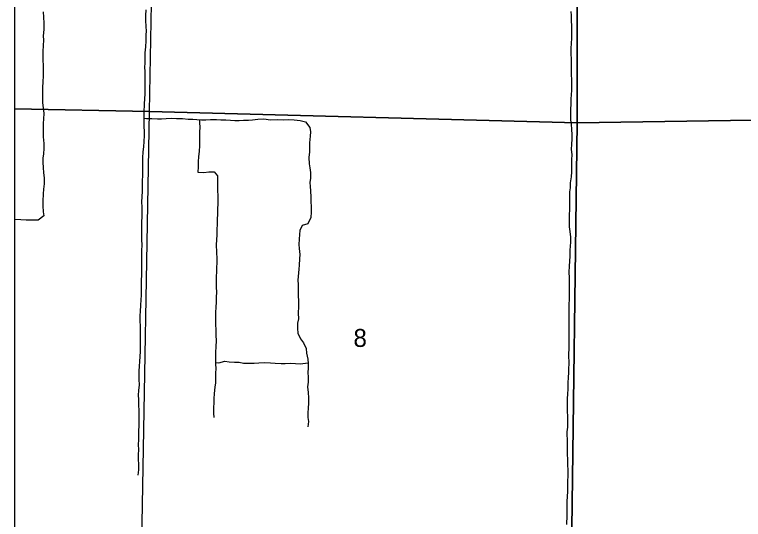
# Model space of a CAD drawing. Extents: x 1772825 to 1773716, y 1138558 to 1139032.
# Drawn here: x 1772825.358 to 1772826.207, y 1138563.179 to 1138563.767 of the extents above; entities that cross this region are included whole.
import ezdxf

# ---------------------------------------------------------------- set-up
doc = ezdxf.new("R2010")
doc.units = 0
for name, color, linetype in [('GM_X_Minor_River', 7, 'Continuous'), ('GM_X_Section', 7, 'Continuous'), ('GM_X_Section_Text', 7, 'Continuous'), ('GM_X_Township', 7, 'Continuous')]:
    doc.layers.add(name, color=color, linetype=linetype)

msp = doc.modelspace()

# ---------------------------------------------------------------- linework, layer by layer
at = {"layer": 'GM_X_Minor_River'}
for points in [[(1772825.51054, 1138563.77204), (1772825.51032, 1138563.76559), (1772825.51029, 1138563.76009), (1772825.51083, 1138563.75231), (1772825.511, 1138563.74757), (1772825.51079, 1138563.74282), (1772825.51057, 1138563.73599), (1772825.51016, 1138563.72917), (1772825.50975, 1138563.72215), (1772825.50953, 1138563.71494), (1772825.50951, 1138563.71001), (1772825.5093, 1138563.70527), (1772825.50947, 1138563.70034), (1772825.50938, 1138563.68004), (1772825.50955, 1138563.67397), (1772825.50934, 1138563.66904), (1772825.50893, 1138563.6624), (1772825.50851, 1138563.65292), (1772825.5083, 1138563.6478), (1772825.50827, 1138563.64097), (1772825.50844, 1138563.63604), (1772825.50861, 1138563.63091), (1772825.50877, 1138563.62598), (1772825.50836, 1138563.61877), (1772825.50796, 1138563.6127), (1772825.50737, 1138563.60664), (1772825.50696, 1138563.59981), (1772825.50675, 1138563.59488), (1772825.50672, 1138563.58957), (1772825.50689, 1138563.58426), (1772825.50687, 1138563.57932), (1772825.50665, 1138563.57288), (1772825.50644, 1138563.56813), (1772825.50641, 1138563.56149)], [(1772825.39115, 1138563.76976), (1772825.3915, 1138563.76369), (1772825.39185, 1138563.75667), (1772825.39182, 1138563.74946), (1772825.39122, 1138563.74206), (1772825.39139, 1138563.73675), (1772825.39136, 1138563.73049), (1772825.39095, 1138563.72367), (1772825.39074, 1138563.71874), (1772825.39072, 1138563.71361), (1772825.39107, 1138563.70735), (1772825.39102, 1138563.69483), (1772825.3908, 1138563.68857), (1772825.39058, 1138563.68118), (1772825.39051, 1138563.66429), (1772825.39124, 1138563.65784), (1772825.39178, 1138563.65196), (1772825.39156, 1138563.64475), (1772825.39135, 1138563.64001), (1772825.39114, 1138563.63451), (1772825.39112, 1138563.62958)], [(1772826.00546, 1138563.77025), (1772826.00582, 1138563.76551), (1772826.00598, 1138563.76019), (1772826.00633, 1138563.75279), (1772826.00649, 1138563.7452), (1772826.00627, 1138563.73876), (1772826.00587, 1138563.73326), (1772826.00546, 1138563.72719), (1772826.00563, 1138563.72036), (1772826.00579, 1138563.71524), (1772826.00577, 1138563.7103), (1772826.00593, 1138563.70385), (1772826.00591, 1138563.69721), (1772826.00625, 1138563.69019), (1772826.00642, 1138563.68545), (1772826.00639, 1138563.67843), (1772826.00599, 1138563.67312), (1772826.00559, 1138563.66838), (1772826.00538, 1138563.66231), (1772826.00535, 1138563.65643), (1772826.0053, 1138563.64391), (1772826.00585, 1138563.63898), (1772826.0062, 1138563.63272), (1772826.00674, 1138563.62702), (1772826.00672, 1138563.62171), (1772826.0065, 1138563.61564), (1772826.0061, 1138563.60938), (1772826.00664, 1138563.6035), (1772826.00643, 1138563.59762), (1772826.00639, 1138563.58814), (1772826.00618, 1138563.5834), (1772826.00577, 1138563.57752), (1772826.00498, 1138563.5705), (1772826.00477, 1138563.565), (1772826.00418, 1138563.56026), (1772826.00396, 1138563.55211), (1772826.00412, 1138563.54509), (1772826.0041, 1138563.53996), (1772826.00369, 1138563.53295), (1772826.00366, 1138563.52707), (1772826.00382, 1138563.51929), (1772826.00455, 1138563.51397), (1772826.00509, 1138563.50752), (1772826.00507, 1138563.50145), (1772826.00427, 1138563.49235), (1772826.00424, 1138563.48552), (1772826.00403, 1138563.47907), (1772826.00381, 1138563.47395), (1772826.0034, 1138563.46618), (1772826.00357, 1138563.46048), (1772826.00332, 1138563.40358), (1772826.00311, 1138563.39883), (1772826.00327, 1138563.39125), (1772826.00325, 1138563.38518), (1772826.00321, 1138563.37797), (1772826.0028, 1138563.37057), (1772826.00314, 1138563.35995), (1772826.00293, 1138563.35445), (1772826.00272, 1138563.3497), (1772826.00231, 1138563.34402), (1772826.00209, 1138563.33776), (1772826.00206, 1138563.33055), (1772826.00166, 1138563.32505), (1772826.00145, 1138563.31898), (1772826.00123, 1138563.31177), (1772826.00139, 1138563.30494), (1772826.00155, 1138563.2983), (1772826.00171, 1138563.2928), (1772826.0015, 1138563.28597), (1772826.00109, 1138563.28066), (1772826.00142, 1138563.26814), (1772826.00121, 1138563.2634), (1772826.00136, 1138563.25524), (1772826.00152, 1138563.24822), (1772826.00169, 1138563.24348), (1772826.00204, 1138563.23494), (1772826.00201, 1138563.22944), (1772826.0018, 1138563.22337), (1772826.00175, 1138563.21142), (1772826.00115, 1138563.20478), (1772826.00094, 1138563.19985), (1772826.00072, 1138563.19359), (1772826.00089, 1138563.18866), (1772826.00087, 1138563.18316), (1772826.00044, 1138563.17292)], [(1772825.50829, 1138563.64609), (1772825.51151, 1138563.64551), (1772825.51776, 1138563.64567), (1772825.52421, 1138563.64526), (1772825.52913, 1138563.64542), (1772825.53444, 1138563.64578), (1772825.54012, 1138563.64594), (1772825.54657, 1138563.64572), (1772825.55358, 1138563.64569), (1772825.56002, 1138563.6449), (1772825.56532, 1138563.64468), (1772825.57025, 1138563.64447), (1772825.57555, 1138563.64425), (1772825.58048, 1138563.64423), (1772825.58597, 1138563.64458), (1772825.59298, 1138563.64436), (1772825.5981, 1138563.64396), (1772825.60397, 1138563.64412), (1772825.60928, 1138563.64352), (1772825.6142, 1138563.64331), (1772825.61951, 1138563.64347), (1772825.62444, 1138563.64383), (1772825.63031, 1138563.6438), (1772825.63505, 1138563.64416), (1772825.64111, 1138563.6447), (1772825.64794, 1138563.64505), (1772825.6557, 1138563.64406), (1772825.66347, 1138563.6444), (1772825.67086, 1138563.64418), (1772825.67636, 1138563.64434), (1772825.68337, 1138563.64412), (1772825.69056, 1138563.64333), (1772825.69681, 1138563.64159), (1772825.70171, 1138563.6353), (1772825.70244, 1138563.62999), (1772825.70223, 1138563.62487), (1772825.70144, 1138563.6171), (1772825.70123, 1138563.61141), (1772825.7014, 1138563.60666), (1772825.70061, 1138563.60003), (1772825.70077, 1138563.59301), (1772825.7017, 1138563.58807), (1772825.70243, 1138563.58276), (1772825.7024, 1138563.57612), (1772825.70181, 1138563.57119), (1772825.70198, 1138563.56625), (1772825.70234, 1138563.56151), (1772825.70269, 1138563.55411), (1772825.70286, 1138563.5488), (1772825.7034, 1138563.54272), (1772825.70318, 1138563.53647), (1772825.70278, 1138563.5304), (1772825.69952, 1138563.52283), (1772825.69288, 1138563.52096), (1772825.69021, 1138563.51509), (1772825.68962, 1138563.51035), (1772825.68922, 1138563.50504), (1772825.689, 1138563.49897), (1772825.68936, 1138563.49404), (1772825.6899, 1138563.48721), (1772825.68969, 1138563.48228), (1772825.68909, 1138563.47488), (1772825.68888, 1138563.47014), (1772825.68768, 1138563.45725), (1772825.68804, 1138563.45231), (1772825.68799, 1138563.4396), (1772825.68834, 1138563.43277), (1772825.6885, 1138563.42651), (1772825.68828, 1138563.41893), (1772825.68844, 1138563.41247), (1772825.68747, 1138563.40736), (1772825.68745, 1138563.4011), (1772825.6878, 1138563.39559), (1772825.69081, 1138563.38913), (1772825.6942, 1138563.38437), (1772825.69739, 1138563.37772), (1772825.69774, 1138563.3724), (1772825.69923, 1138563.36519), (1772825.69978, 1138563.36025), (1772825.69956, 1138563.35494), (1772825.69954, 1138563.34963), (1772825.69971, 1138563.34432), (1772825.69968, 1138563.33863), (1772825.69909, 1138563.33313), (1772825.69982, 1138563.32668), (1772825.70018, 1138563.32023), (1772825.69996, 1138563.31378), (1772825.69956, 1138563.30866), (1772825.69934, 1138563.30259), (1772825.69951, 1138563.29747), (1772825.70006, 1138563.29253), (1772825.69946, 1138563.28665)], [(1772825.57313, 1138563.64435), (1772825.57326, 1138563.64104), (1772825.57343, 1138563.63497), (1772825.57341, 1138563.63022), (1772825.57319, 1138563.62397), (1772825.57315, 1138563.61391), (1772825.57274, 1138563.60746), (1772825.57196, 1138563.60102), (1772825.57155, 1138563.59571), (1772825.57153, 1138563.58945), (1772825.57131, 1138563.58319), (1772825.57813, 1138563.58278), (1772825.5842, 1138563.58332), (1772825.59045, 1138563.58367), (1772825.59403, 1138563.57891), (1772825.59419, 1138563.57227), (1772825.59436, 1138563.56696), (1772825.59433, 1138563.56108), (1772825.5945, 1138563.55614), (1772825.59467, 1138563.5514), (1772825.59446, 1138563.54666), (1772825.59405, 1138563.53983), (1772825.59398, 1138563.52238), (1772825.59357, 1138563.5165), (1772825.59336, 1138563.51043), (1772825.59295, 1138563.50379), (1772825.59274, 1138563.49886), (1772825.59308, 1138563.48938), (1772825.59324, 1138563.48255), (1772825.59318, 1138563.46718), (1772825.59277, 1138563.46168), (1772825.59272, 1138563.44935), (1772825.59288, 1138563.44328), (1772825.59248, 1138563.43759), (1772825.59265, 1138563.4319), (1772825.59224, 1138563.42564), (1772825.59203, 1138563.41995), (1772825.59181, 1138563.41256), (1772825.59197, 1138563.40611), (1772825.59232, 1138563.39927), (1772825.5921, 1138563.39283), (1772825.59264, 1138563.38713), (1772825.59223, 1138563.37955), (1772825.59202, 1138563.37329), (1772825.59196, 1138563.35963), (1772825.59213, 1138563.35432), (1772825.59191, 1138563.34901), (1772825.59189, 1138563.34256), (1772825.59168, 1138563.33763), (1772825.59109, 1138563.33251), (1772825.5903, 1138563.3253), (1772825.59008, 1138563.31923), (1772825.59006, 1138563.31449), (1772825.58966, 1138563.30918), (1772825.58963, 1138563.30235), (1772825.58999, 1138563.29742)], [(1772825.39112, 1138563.62958), (1772825.39129, 1138563.62426), (1772825.39182, 1138563.61648), (1772825.39199, 1138563.61079), (1772825.39177, 1138563.60434), (1772825.39099, 1138563.59923), (1772825.39078, 1138563.59448), (1772825.39132, 1138563.58841), (1772825.39168, 1138563.58253), (1772825.39241, 1138563.57645), (1772825.39219, 1138563.56944), (1772825.39141, 1138563.56337), (1772825.39119, 1138563.55806), (1772825.39097, 1138563.54953), (1772825.39094, 1138563.54383), (1772825.39129, 1138563.537), (1772825.39184, 1138563.53226), (1772825.38538, 1138563.52717), (1772825.37155, 1138563.52723), (1772825.36511, 1138563.52764), (1772825.35866, 1138563.52786), (1772825.35791, 1138563.52752)], [(1772825.50641, 1138563.56149), (1772825.506, 1138563.5541), (1772825.50579, 1138563.54879), (1772825.50595, 1138563.54215), (1772825.50612, 1138563.53703), (1772825.5061, 1138563.53133), (1772825.50588, 1138563.52489), (1772825.50567, 1138563.52015), (1772825.50563, 1138563.51009), (1772825.50579, 1138563.50459), (1772825.50595, 1138563.49795), (1772825.50574, 1138563.49169), (1772825.5057, 1138563.48202), (1772825.50586, 1138563.47481), (1772825.50564, 1138563.46931), (1772825.50562, 1138563.46399), (1772825.5054, 1138563.4566), (1772825.50536, 1138563.44635), (1772825.50514, 1138563.43953), (1772825.50493, 1138563.43479), (1772825.50452, 1138563.42777), (1772825.5043, 1138563.42113), (1772825.5039, 1138563.41582), (1772825.50387, 1138563.40975), (1772825.50404, 1138563.40425), (1772825.50421, 1138563.3995), (1772825.50418, 1138563.39324), (1772825.50397, 1138563.38699), (1772825.50412, 1138563.37959), (1772825.5041, 1138563.37447), (1772825.50389, 1138563.36802), (1772825.50348, 1138563.3629), (1772825.50308, 1138563.35683), (1772825.50249, 1138563.35171), (1772825.50247, 1138563.34678), (1772825.50263, 1138563.34147), (1772825.50299, 1138563.33558), (1772825.5022, 1138563.32895), (1772825.5018, 1138563.32326), (1772825.50216, 1138563.31851), (1772825.50233, 1138563.31339), (1772825.50247, 1138563.30391), (1772825.50245, 1138563.29878), (1772825.50243, 1138563.29385), (1772825.50259, 1138563.2874), (1772825.50238, 1138563.28228), (1772825.50236, 1138563.27735), (1772825.50215, 1138563.27128), (1772825.50193, 1138563.26578), (1772825.5021, 1138563.25971), (1772825.5017, 1138563.2544), (1772825.50186, 1138563.24833), (1772825.50202, 1138563.24283), (1772825.502, 1138563.23638), (1772825.5014, 1138563.23012)], [(1772825.59197, 1138563.36153), (1772825.59575, 1138563.36113), (1772825.60258, 1138563.36299), (1772825.6077, 1138563.36221), (1772825.61414, 1138563.36199), (1772825.61925, 1138563.36178), (1772825.62456, 1138563.3608), (1772825.62986, 1138563.36078), (1772825.63668, 1138563.36055), (1772825.64237, 1138563.36091), (1772825.649, 1138563.36144), (1772825.65601, 1138563.36103), (1772825.66131, 1138563.36082), (1772825.66813, 1138563.36022), (1772825.67287, 1138563.36038), (1772825.67875, 1138563.36054), (1772825.68481, 1138563.36014), (1772825.69049, 1138563.35973), (1772825.6997, 1138563.36094)]]:
    msp.add_lwpolyline(points, dxfattribs=at)
at = {"layer": 'GM_X_Section'}
for p, q in [((1772825.35791, 1138564.14068), (1772825.35791, 1138563.65686)), ((1772825.35791, 1138563.65686), (1772825.35791, 1138563.15498))]:
    msp.add_line(p, q, dxfattribs=at)
for points in [[(1772825.35791, 1138563.65686), (1772825.51518, 1138563.65396), (1772825.52387, 1138564.13628), (1772825.51345, 1138564.13656), (1772825.35791, 1138564.14068)], [(1772825.35791, 1138563.15498), (1772825.50612, 1138563.15213), (1772825.51518, 1138563.65396), (1772825.35791, 1138563.65686)]]:
    msp.add_lwpolyline(points, dxfattribs=at)
for points in [[(1772825.52387, 1138564.13628), (1772826.01263, 1138564.12772), (1772826.01279, 1138563.64058), (1772825.51518, 1138563.65396)], [(1772826.50366, 1138564.12386), (1772826.49778, 1138563.64814), (1772826.01279, 1138563.64058), (1772826.01263, 1138564.12772)], [(1772825.51518, 1138563.65396), (1772826.01279, 1138563.64058), (1772826.00619, 1138563.13835), (1772825.50612, 1138563.15213)], [(1772826.01279, 1138563.64058), (1772826.49778, 1138563.64814), (1772826.50172, 1138563.14184), (1772826.00619, 1138563.13835)]]:
    msp.add_lwpolyline(points, close=True, dxfattribs=at)
at = {"layer": 'GM_X_Township'}
msp.add_line((1772825.35791, 1138564.139), (1772825.35791, 1138561.13797), dxfattribs=at)

# ---------------------------------------------------------------- texts
at = {"layer": 'GM_X_Section_Text'}
msp.add_text('8', height=0.02093, rotation=0.00001, dxfattribs=at).set_placement((1772825.7525, 1138563.37957))

doc.saveas('drawing.dxf')
